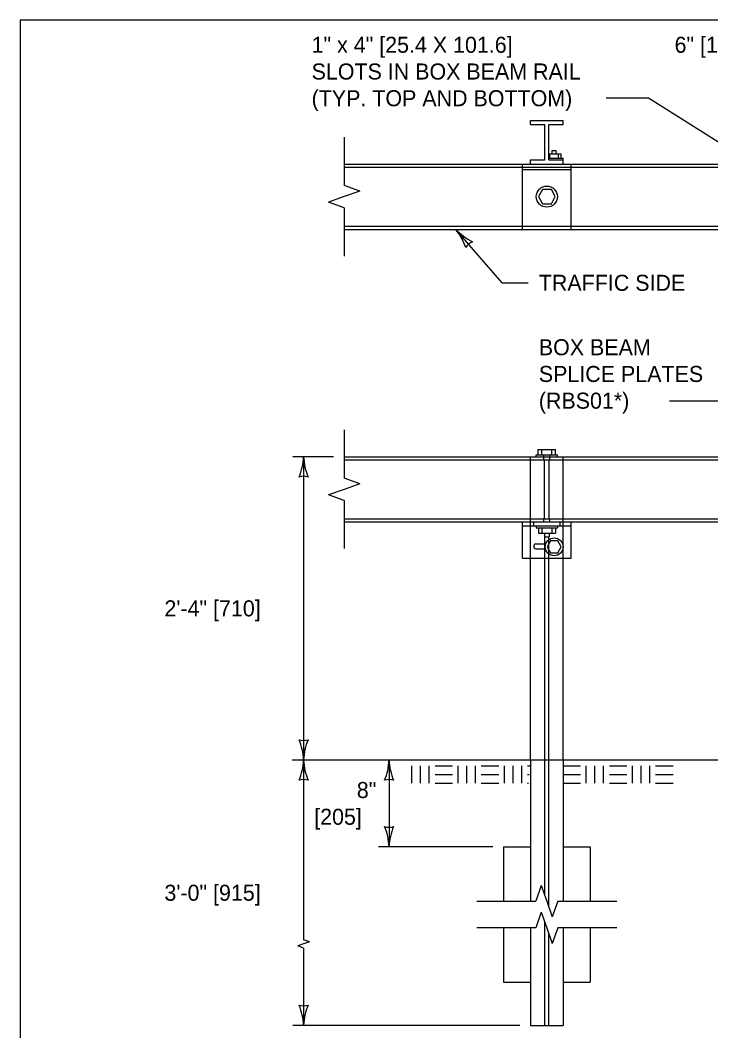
# Model space of a CAD drawing. Extents: x 49991.4 to 50021, y 49987.6 to 50011.4.
# Drawn here: x 50009.737 to 50012.323, y 50004.382 to 50008.165 of the extents above; entities that cross this region are included whole.
import ezdxf

# ---------------------------------------------------------------- set-up
doc = ezdxf.new("R2010")
doc.units = 0
for name, color, linetype in [('Level 1', 7, 'Continuous'), ('Level 2', 7, 'Continuous'), ('Level 3', 7, 'Continuous'), ('Level 4', 7, 'Continuous'), ('Level 6', 7, 'Continuous')]:
    doc.layers.add(name, color=color, linetype=linetype)

msp = doc.modelspace()

# ---------------------------------------------------------------- linework, layer by layer
at = {"layer": 'Level 1'}
for p, q in [((50011.6484, 50007.7742), (50011.6484, 50007.7888)), ((50011.6484, 50007.7888), (50011.7702, 50007.7888)), ((50011.6484, 50007.7742), (50011.7014, 50007.7742)), ((50011.7014, 50007.6422), (50011.7014, 50007.7742)), ((50011.7172, 50007.6422), (50011.7172, 50007.7742)), ((50011.7172, 50007.7742), (50011.7702, 50007.7742)), ((50011.7702, 50007.7742), (50011.7702, 50007.7888)), ((50011.6484, 50007.6422), (50011.7014, 50007.6422)), ((50011.6484, 50007.6264), (50011.6484, 50007.6422)), ((50011.7172, 50007.6649), (50011.7635, 50007.6649)), ((50011.7172, 50007.6485), (50011.7699, 50007.6485)), ((50011.7172, 50007.6422), (50011.7702, 50007.6422)), ((50011.7211, 50007.6485), (50011.7211, 50007.6649)), ((50011.7526, 50007.6485), (50011.7526, 50007.6649)), ((50011.7635, 50007.6485), (50011.7635, 50007.6649)), ((50011.7699, 50007.6422), (50011.7699, 50007.6485)), ((50011.7702, 50007.6264), (50011.7702, 50007.6422)), ((50010.9506, 50007.6264), (50013.131, 50007.6264)), ((50010.9506, 50007.3818), (50013.131, 50007.3818)), ((50011.6774, 50006.5384), (50011.6774, 50006.5581)), ((50011.6774, 50006.5581), (50011.7414, 50006.5581)), ((50011.6905, 50006.5384), (50011.6905, 50006.5581)), ((50011.7282, 50006.5384), (50011.7282, 50006.5581)), ((50011.7414, 50006.5384), (50011.7414, 50006.5581)), ((50010.9506, 50006.5309), (50013.131, 50006.5309)), ((50011.6692, 50006.5384), (50011.749, 50006.5384)), ((50011.6692, 50006.5309), (50011.6692, 50006.5384)), ((50011.749, 50006.5309), (50011.749, 50006.5384)), ((50010.9506, 50006.287), (50013.131, 50006.287)), ((50011.6177, 50006.1508), (50011.6177, 50006.287)), ((50011.8006, 50006.1508), (50011.8006, 50006.287)), ((50011.6177, 50006.2724), (50011.8006, 50006.2724)), ((50011.6693, 50006.2724), (50011.6693, 50006.2649)), ((50011.6693, 50006.2649), (50011.749, 50006.2649)), ((50011.6775, 50006.2649), (50011.6775, 50006.2452)), ((50011.6775, 50006.2452), (50011.7414, 50006.2452)), ((50011.6906, 50006.2649), (50011.6906, 50006.2452)), ((50011.7283, 50006.2649), (50011.7283, 50006.2452)), ((50011.7414, 50006.2649), (50011.7414, 50006.2452)), ((50011.749, 50006.2724), (50011.749, 50006.2649)), ((50011.6681, 50006.2045), (50011.7053, 50006.2045)), ((50011.6681, 50006.1859), (50011.7043, 50006.1859)), ((50011.6177, 50006.1508), (50011.8006, 50006.1508)), ((50011.6482, 50005.3957), (50011.6482, 50006.1508)), ((50011.7701, 50005.3957), (50011.7701, 50006.1508)), ((50015.0681, 50005.3957), (50010.756, 50005.3957)), ((50011.204, 50005.3091), (50011.204, 50005.3741)), ((50011.2365, 50005.3091), (50011.2365, 50005.3741)), ((50011.269, 50005.3091), (50011.269, 50005.3741)), ((50011.2906, 50005.3741), (50011.3557, 50005.3741)), ((50011.3774, 50005.3091), (50011.3774, 50005.3741)), ((50011.4098, 50005.3091), (50011.4098, 50005.3741)), ((50011.4423, 50005.3091), (50011.4423, 50005.3741)), ((50011.464, 50005.3741), (50011.529, 50005.3741)), ((50011.5507, 50005.3091), (50011.5507, 50005.3741)), ((50011.5832, 50005.3091), (50011.5832, 50005.3741)), ((50011.6157, 50005.3091), (50011.6157, 50005.3741)), ((50011.6374, 50005.3741), (50011.6374, 50005.3741)), ((50011.7701, 50005.3741), (50011.7701, 50005.3741)), ((50011.7701, 50005.3741), (50011.835, 50005.3741)), ((50011.8568, 50005.3091), (50011.8568, 50005.3741)), ((50011.8893, 50005.3091), (50011.8893, 50005.3741)), ((50011.9218, 50005.3091), (50011.9218, 50005.3741)), ((50011.9434, 50005.3741), (50012.0084, 50005.3741)), ((50012.0301, 50005.3091), (50012.0301, 50005.3741)), ((50012.0626, 50005.3091), (50012.0626, 50005.3741)), ((50012.0951, 50005.3091), (50012.0951, 50005.3741)), ((50012.1168, 50005.3741), (50012.1818, 50005.3741)), ((50011.2906, 50005.3416), (50011.3557, 50005.3416)), ((50011.464, 50005.3416), (50011.529, 50005.3416)), ((50011.7701, 50005.3416), (50011.835, 50005.3416)), ((50011.9434, 50005.3416), (50012.0084, 50005.3416)), ((50012.1168, 50005.3416), (50012.1818, 50005.3416)), ((50011.2906, 50005.3091), (50011.3557, 50005.3091)), ((50011.464, 50005.3091), (50011.529, 50005.3091)), ((50011.7701, 50005.3091), (50011.835, 50005.3091)), ((50011.9434, 50005.3091), (50012.0084, 50005.3091)), ((50012.1168, 50005.3091), (50012.1818, 50005.3091))]:
    msp.add_line(p, q, dxfattribs=at)
for points in [[(50020.9378, 50008.1646), (50009.7374, 50008.1646), (50009.7374, 49999.8856), (50020.9378, 49999.8856)], [(50011.6929, 50007.4777), (50011.7263, 50007.4777), (50011.741, 50007.5044), (50011.7263, 50007.5311), (50011.6929, 50007.5311), (50011.6782, 50007.5044)], [(50011.7226, 50006.1713), (50011.7507, 50006.1713), (50011.763, 50006.1936), (50011.7507, 50006.2161), (50011.7226, 50006.2161), (50011.7103, 50006.1936)]]:
    msp.add_lwpolyline(points, close=True, dxfattribs=at)
for points in [[(50011.7295, 50007.6649), (50011.7295, 50007.6767)], [(50011.7295, 50007.6767), (50011.7437, 50007.6767)], [(50011.7437, 50007.6649), (50011.7437, 50007.6767)], [(50011.7006, 50006.2452), (50011.7006, 50006.231)], [(50011.7176, 50006.2452), (50011.7176, 50006.231)], [(50011.7006, 50006.231), (50011.7176, 50006.231)], [(50011.6374, 50005.3741), (50011.6462, 50005.3741)], [(50011.6482, 50005.3957), (50011.6482, 50005.3957)], [(50011.7701, 50005.3957), (50011.7701, 50005.3957)], [(50011.6374, 50005.3416), (50011.6432, 50005.3416)], [(50011.6374, 50005.3091), (50011.6402, 50005.3091)]]:
    msp.add_lwpolyline(points, dxfattribs=at)
for centre, radius in [((50011.7093, 50007.5043), 0.0395), ((50011.7367, 50006.1936), 0.0333)]:
    msp.add_circle(centre, radius, dxfattribs=at)
msp.add_arc((50011.6695, 50006.1952), 0.00938, 98.5498, 261.4502, dxfattribs=at)
at = {"layer": 'Level 3'}
for p, q in [((50010.9106, 50006.5309), (50010.7586, 50006.5309)), ((50010.7986, 50006.5309), (50010.7986, 50005.3957)), ((50010.7986, 50005.3957), (50010.7986, 50004.723)), ((50011.1186, 50005.3957), (50011.1186, 50005.0708)), ((50011.5066, 50005.0708), (50011.0786, 50005.0708)), ((50010.7986, 50004.7075), (50010.7767, 50004.6997)), ((50010.7986, 50004.692), (50010.7767, 50004.6997)), ((50010.8206, 50004.7153), (50010.7986, 50004.723)), ((50010.8206, 50004.7153), (50010.7986, 50004.7075)), ((50010.7986, 50004.692), (50010.7986, 50004.4022)), ((50011.6082, 50004.4022), (50010.7586, 50004.4022))]:
    msp.add_line(p, q, dxfattribs=at)
for points in [[(50012.0896, 50007.8726), (50011.9321, 50007.8726)], [(50012.677, 50007.5039), (50012.0896, 50007.8726)], [(50011.5421, 50007.1818), (50011.3682, 50007.3818)], [(50011.5421, 50007.1818), (50011.6393, 50007.1818)], [(50012.1682, 50006.7406), (50012.4527, 50006.7406)]]:
    msp.add_lwpolyline(points, dxfattribs=at)
for centre, radius, start, end in [((50011.1946, 50007.243), 0.2223, 18.463, 38.6465), ((50011.5363, 50007.5432), 0.233, 223.8343, 243.0841), ((50011.1946, 50007.243), 0.2223, 18.463, 38.6465), ((50011.5363, 50007.5432), 0.233, 223.8343, 243.0841), ((50011.4523, 50007.285), 0.0548, 113.1458, 148.8681), ((50011.4523, 50007.285), 0.0548, 113.1458, 148.8681), ((50010.5765, 50006.5401), 0.2223, 337.456, 357.6395), ((50011.0313, 50006.5424), 0.233, 182.8273, 202.0772), ((50010.7986, 50006.4027), 0.0548, 72.1388, 107.8612), ((50010.7986, 50005.5239), 0.0548, 252.1388, 287.8612), ((50010.5659, 50005.3842), 0.233, 2.8273, 22.0772), ((50011.0207, 50005.3865), 0.2223, 157.456, 177.6395), ((50010.5765, 50005.4049), 0.2223, 337.456, 357.6395), ((50011.0313, 50005.4072), 0.233, 182.8273, 202.0772), ((50010.8965, 50005.4049), 0.2223, 337.456, 357.6395), ((50011.3513, 50005.4072), 0.233, 182.8273, 202.0772), ((50010.7986, 50005.2675), 0.0548, 72.1388, 107.8612), ((50011.1186, 50005.2675), 0.0548, 72.1388, 107.8612), ((50011.1186, 50005.199), 0.0548, 252.1388, 287.8612), ((50010.8859, 50005.0593), 0.233, 2.8273, 22.0772), ((50011.3407, 50005.0616), 0.2223, 157.456, 177.6395), ((50010.7986, 50004.5304), 0.0548, 252.1388, 287.8612), ((50010.5659, 50004.3907), 0.233, 2.8273, 22.0772), ((50011.0207, 50004.393), 0.2223, 157.456, 177.6395)]:
    msp.add_arc(centre, radius, start, end, dxfattribs=at)
at = {"layer": 'Level 4'}
for p, q in [((50010.9506, 50007.615), (50013.131, 50007.615)), ((50011.6177, 50007.3818), (50011.6177, 50007.6264)), ((50011.6178, 50007.6053), (50011.8006, 50007.6053)), ((50011.8006, 50007.3818), (50011.8006, 50007.6264)), ((50010.9506, 50007.3932), (50013.131, 50007.3932)), ((50010.9506, 50006.5198), (50013.131, 50006.5198)), ((50011.6482, 50006.1508), (50011.6482, 50006.5309)), ((50011.6978, 50006.5198), (50011.6978, 50006.5384)), ((50011.7006, 50006.2981), (50011.7006, 50006.5198)), ((50011.7176, 50006.2981), (50011.7176, 50006.5198)), ((50011.7204, 50006.5198), (50011.7204, 50006.5384)), ((50011.77, 50006.1508), (50011.77, 50006.5309)), ((50010.9506, 50006.2981), (50013.131, 50006.2981)), ((50011.6601, 50006.2724), (50011.6601, 50006.287)), ((50011.6978, 50006.287), (50011.6978, 50006.2981)), ((50011.7204, 50006.287), (50011.7204, 50006.2981)), ((50011.7588, 50006.2724), (50011.7588, 50006.287)), ((50011.7015, 50004.889), (50011.7015, 50006.231)), ((50011.7167, 50004.8461), (50011.7167, 50006.231)), ((50011.6482, 50005.3957), (50011.6482, 50004.8676)), ((50011.7701, 50005.3957), (50011.7701, 50004.8676)), ((50011.5466, 50005.0708), (50011.6482, 50005.0708)), ((50011.5466, 50005.0708), (50011.5466, 50004.8676)), ((50011.7701, 50005.0708), (50011.8716, 50005.0708)), ((50011.8716, 50005.0708), (50011.8716, 50004.8676)), ((50011.5466, 50004.7678), (50011.5466, 50004.5647)), ((50011.6482, 50004.7678), (50011.6482, 50004.4022)), ((50011.7015, 50004.4022), (50011.7015, 50004.7893)), ((50011.7701, 50004.7678), (50011.7701, 50004.4022)), ((50011.8716, 50004.7678), (50011.8716, 50004.5647)), ((50011.7167, 50004.4022), (50011.7167, 50004.7464)), ((50011.5466, 50004.5647), (50011.6482, 50004.5647)), ((50011.7701, 50004.5647), (50011.8716, 50004.5647)), ((50011.6482, 50004.4022), (50011.7701, 50004.4022))]:
    msp.add_line(p, q, dxfattribs=at)
at = {"layer": 'Level 6'}
for p, q in [((50010.9506, 50007.7264), (50010.9506, 50007.5456)), ((50011.0091, 50007.5249), (50010.9506, 50007.5456)), ((50010.9506, 50007.5042), (50010.8922, 50007.4834)), ((50011.0091, 50007.5249), (50010.9506, 50007.5042)), ((50010.9506, 50007.4627), (50010.8922, 50007.4834)), ((50010.9506, 50007.4627), (50010.9506, 50007.2818)), ((50010.9506, 50006.6309), (50010.9506, 50006.4501)), ((50011.0091, 50006.4293), (50010.9506, 50006.4501)), ((50010.9506, 50006.4086), (50010.8922, 50006.3879)), ((50011.0091, 50006.4293), (50010.9506, 50006.4086)), ((50010.9506, 50006.3672), (50010.8922, 50006.3879)), ((50010.9506, 50006.3672), (50010.9506, 50006.187)), ((50011.6884, 50004.9261), (50011.6677, 50004.8676)), ((50011.6884, 50004.9261), (50011.7091, 50004.8676)), ((50011.4466, 50004.8676), (50011.6677, 50004.8676)), ((50011.7091, 50004.8676), (50011.7298, 50004.8091)), ((50011.7506, 50004.8676), (50011.7298, 50004.8091)), ((50011.7506, 50004.8676), (50011.9716, 50004.8676)), ((50011.6884, 50004.8263), (50011.6677, 50004.7678)), ((50011.6884, 50004.8263), (50011.7091, 50004.7678)), ((50011.6677, 50004.7678), (50011.4466, 50004.7678)), ((50011.7091, 50004.7678), (50011.7298, 50004.7093)), ((50011.7506, 50004.7678), (50011.7298, 50004.7093)), ((50011.9716, 50004.7678), (50011.7506, 50004.7678))]:
    msp.add_line(p, q, dxfattribs=at)

# ---------------------------------------------------------------- texts
at = {"layer": 'Level 2'}
for s, p in [('1" x 4" [25.4 X 101.6] ', (50010.8285, 50008.0426)), ('6" [152]', (50012.1876, 50008.0426)), ('SLOTS IN BOX BEAM RAIL', (50010.8285, 50007.9426)), ('(TYP. TOP AND BOTTOM)', (50010.8285, 50007.8426)), ('TRAFFIC SIDE', (50011.6793, 50007.1518)), ('BOX BEAM', (50011.6793, 50006.9106)), ('SPLICE PLATES', (50011.6793, 50006.8106)), ('(RBS01*)', (50011.6793, 50006.7106)), ('2\'-4" [710]', (50010.2774, 50005.9333)), ('8"', (50010.9979, 50005.2533)), ('[205]', (50010.8382, 50005.1533)), ('3\'-0" [915]', (50010.2774, 50004.8689))]:
    msp.add_text(s, height=0.06, dxfattribs=at).set_placement(p)

doc.saveas('drawing.dxf')
